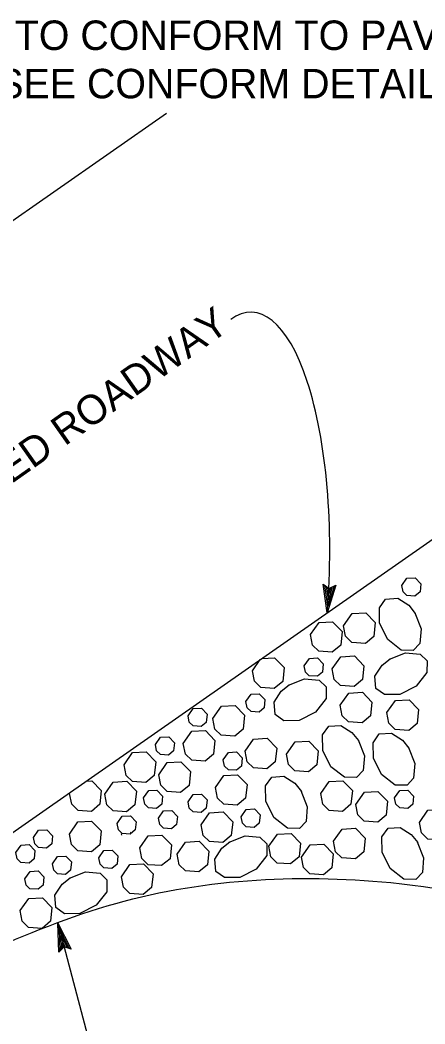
# Model space of a CAD drawing. Extents: x 6709491 to 6710959, y 1869789 to 1870763.
# Drawn here: x 6710515.2 to 6710597.8, y 1870323.8 to 1870528.2 of the extents above; entities that cross this region are included whole.
import ezdxf

# ---------------------------------------------------------------- set-up
doc = ezdxf.new("R2010")
doc.units = 0
for name, color, linetype in [('56 Stg 3 Anno', 7, 'Continuous'), ('57 Undefined', 7, 'Continuous'), ('60 Nongeo Data', 7, 'Continuous')]:
    doc.layers.add(name, color=color, linetype=linetype)

msp = doc.modelspace()

# ---------------------------------------------------------------- linework, layer by layer
at = {"layer": '56 Stg 3 Anno'}
for p, q in [((6710577.87, 1870407.51), (6710577.07, 1870413.35)), ((6710577.07, 1870413.35), (6710577.07, 1870413.35)), ((6710577.07, 1870413.35), (6710578.28, 1870412.48)), ((6710577.98, 1870408.84), (6710577.39, 1870413.1)), ((6710578.09, 1870410.15), (6710577.71, 1870412.9)), ((6710579.62, 1870413.14), (6710577.87, 1870407.51)), ((6710579.26, 1870412.96), (6710577.98, 1870408.83)), ((6710578.2, 1870411.47), (6710578.04, 1870412.65)), ((6710578.9, 1870412.77), (6710578.09, 1870410.15)), ((6710578.56, 1870412.63), (6710578.2, 1870411.47)), ((6710578.28, 1870412.48), (6710579.62, 1870413.14)), ((6710579.62, 1870413.14), (6710579.62, 1870413.14)), ((6710577.87, 1870407.51), (6710577.87, 1870407.51)), ((6710522.92, 1870344.3), (6710533.94, 1870302.96)), ((6710523.16, 1870338.4), (6710522.92, 1870344.3)), ((6710522.92, 1870344.3), (6710522.92, 1870344.3)), ((6710522.92, 1870344.3), (6710525.64, 1870339.06)), ((6710523.44, 1870338.69), (6710523.26, 1870343.02)), ((6710523.27, 1870343.01), (6710525.25, 1870339.19)), ((6710523.72, 1870339), (6710523.6, 1870341.74)), ((6710523.6, 1870341.74), (6710524.88, 1870339.27)), ((6710523.99, 1870339.25), (6710523.94, 1870340.46)), ((6710523.94, 1870340.46), (6710524.49, 1870339.4)), ((6710524.21, 1870339.48), (6710523.16, 1870338.4)), ((6710523.16, 1870338.4), (6710523.16, 1870338.4)), ((6710525.64, 1870339.06), (6710524.21, 1870339.48)), ((6710525.64, 1870339.06), (6710525.64, 1870339.06))]:
    msp.add_line(p, q, dxfattribs=at)
msp.add_ellipse((6710561.04, 1870416.49), major_axis=(1.41, 52.24), ratio=0.331, start_param=4.548521, end_param=6.530169, dxfattribs=at)
at = {"layer": '60 Nongeo Data'}
for p, q in [((6710438.76, 1870435.1), (6710545.07, 1870509.22)), ((6710451.72, 1870319.56), (6710722.11, 1870508.07))]:
    msp.add_line(p, q, dxfattribs=at)
for points in [[(6710593.08, 1870413.05), (6710594.12, 1870414.54), (6710595.79, 1870414.63), (6710596.95, 1870413.43), (6710596.78, 1870411.75), (6710595.75, 1870410.89), (6710594.11, 1870411.01), (6710593.33, 1870411.76), (6710593.08, 1870413.05)], [(6710595.71, 1870407.53), (6710597, 1870404.28), (6710596.74, 1870401.29), (6710595.39, 1870399.87), (6710592.96, 1870399.92), (6710590.21, 1870402.07), (6710588.54, 1870405.41), (6710588.49, 1870408.54), (6710589.74, 1870410.31), (6710592.25, 1870410.48), (6710594.48, 1870409.05), (6710595.79, 1870407.4)], [(6710581.2, 1870404.88), (6710582.94, 1870407.36), (6710585.71, 1870407.52), (6710587.65, 1870405.52), (6710587.37, 1870402.71), (6710585.65, 1870401.28), (6710582.91, 1870401.48), (6710581.62, 1870402.73), (6710581.2, 1870404.88)], [(6710574.45, 1870403.07), (6710576.19, 1870405.54), (6710578.97, 1870405.7), (6710580.9, 1870403.7), (6710580.62, 1870400.9), (6710578.9, 1870399.47), (6710576.16, 1870399.67), (6710574.87, 1870400.92), (6710574.45, 1870403.07)], [(6710590.55, 1870398.08), (6710593.81, 1870399.37), (6710596.79, 1870399.11), (6710598.21, 1870397.76), (6710598.17, 1870395.33), (6710596.01, 1870392.58), (6710592.68, 1870390.91), (6710589.54, 1870390.86), (6710587.77, 1870392.11), (6710587.6, 1870394.61), (6710589.04, 1870396.85), (6710590.68, 1870398.16)], [(6710564.53, 1870398.21), (6710567.14, 1870398.36), (6710569.07, 1870396.35), (6710568.79, 1870393.55), (6710567.08, 1870392.12), (6710564.34, 1870392.32), (6710563.05, 1870393.57), (6710562.63, 1870395.72)], [(6710562.63, 1870395.72), (6710564.22, 1870397.99)], [(6710564.22, 1870397.99), (6710564.22, 1870397.99)], [(6710573.18, 1870396.74), (6710574.22, 1870398.22), (6710575.89, 1870398.32), (6710577.05, 1870397.12), (6710576.88, 1870395.44), (6710575.85, 1870394.58), (6710574.2, 1870394.7), (6710573.43, 1870395.45), (6710573.18, 1870396.74)], [(6710578.88, 1870396.1), (6710580.62, 1870398.57), (6710583.4, 1870398.73), (6710585.33, 1870396.73), (6710585.05, 1870393.93), (6710583.33, 1870392.5), (6710580.59, 1870392.7), (6710579.3, 1870393.95), (6710578.88, 1870396.1)], [(6710570, 1870392.78), (6710573.25, 1870394.07), (6710576.24, 1870393.81), (6710577.66, 1870392.46), (6710577.62, 1870390.03), (6710575.46, 1870387.28), (6710572.13, 1870385.61), (6710568.99, 1870385.55), (6710567.22, 1870386.81), (6710567.05, 1870389.31), (6710568.49, 1870391.55), (6710570.13, 1870392.86)], [(6710580.52, 1870388.69), (6710582.25, 1870391.17), (6710585.03, 1870391.32), (6710586.96, 1870389.32), (6710586.68, 1870386.52), (6710584.97, 1870385.09), (6710582.23, 1870385.29), (6710580.94, 1870386.54), (6710580.52, 1870388.69)], [(6710561.3, 1870389.46), (6710562.34, 1870390.94), (6710564.01, 1870391.04), (6710565.17, 1870389.84), (6710565, 1870388.15), (6710563.97, 1870387.3), (6710562.33, 1870387.42), (6710561.55, 1870388.17), (6710561.3, 1870389.46)], [(6710590.03, 1870387.18), (6710591.76, 1870389.65), (6710594.54, 1870389.81), (6710596.47, 1870387.81), (6710596.19, 1870385), (6710594.48, 1870383.58), (6710591.74, 1870383.77), (6710590.45, 1870385.03), (6710590.03, 1870387.18)], [(6710549.5, 1870386.51), (6710550.54, 1870388), (6710552.21, 1870388.09), (6710553.36, 1870386.89), (6710553.2, 1870385.21), (6710552.17, 1870384.35), (6710550.52, 1870384.47), (6710549.75, 1870385.22), (6710549.5, 1870386.51)], [(6710554.55, 1870386), (6710556.29, 1870388.48), (6710559.07, 1870388.64), (6710561, 1870386.64), (6710560.72, 1870383.83), (6710559, 1870382.4), (6710556.26, 1870382.6), (6710554.97, 1870383.85), (6710554.55, 1870386)], [(6710548.52, 1870380.9), (6710550.26, 1870383.38), (6710553.03, 1870383.54), (6710554.96, 1870381.53), (6710554.68, 1870378.73), (6710552.97, 1870377.3), (6710550.23, 1870377.5), (6710548.94, 1870378.75), (6710548.52, 1870380.9)], [(6710584.14, 1870381.64), (6710585.43, 1870378.39), (6710585.17, 1870375.4), (6710583.82, 1870373.98), (6710581.39, 1870374.02), (6710578.63, 1870376.18), (6710576.97, 1870379.51), (6710576.91, 1870382.65), (6710578.17, 1870384.42), (6710580.67, 1870384.59), (6710582.91, 1870383.15), (6710584.22, 1870381.51)], [(6710594.45, 1870380.06), (6710595.74, 1870376.81), (6710595.48, 1870373.82), (6710594.13, 1870372.4), (6710591.7, 1870372.45), (6710588.95, 1870374.6), (6710587.28, 1870377.94), (6710587.23, 1870381.07), (6710588.48, 1870382.84), (6710590.98, 1870383.01), (6710593.22, 1870381.58), (6710594.53, 1870379.93)], [(6710542.84, 1870380.68), (6710543.88, 1870382.17), (6710545.55, 1870382.26), (6710546.7, 1870381.06), (6710546.54, 1870379.38), (6710545.51, 1870378.52), (6710543.86, 1870378.64), (6710543.09, 1870379.39), (6710542.84, 1870380.68)], [(6710561.11, 1870379.34), (6710562.85, 1870381.81), (6710565.63, 1870381.97), (6710567.56, 1870379.97), (6710567.28, 1870377.17), (6710565.56, 1870375.74), (6710562.82, 1870375.94), (6710561.53, 1870377.19), (6710561.11, 1870379.34)], [(6710569.58, 1870378.76), (6710571.32, 1870381.24), (6710574.1, 1870381.39), (6710576.03, 1870379.39), (6710575.75, 1870376.59), (6710574.04, 1870375.16), (6710571.29, 1870375.36), (6710570, 1870376.61), (6710569.58, 1870378.76)], [(6710536.45, 1870376.56), (6710538.19, 1870379.04), (6710540.96, 1870379.19), (6710542.89, 1870377.19), (6710542.61, 1870374.39), (6710540.9, 1870372.96), (6710538.16, 1870373.16), (6710536.87, 1870374.41), (6710536.45, 1870376.56)], [(6710556.68, 1870377.61), (6710557.73, 1870379.1), (6710559.39, 1870379.19), (6710560.55, 1870377.99), (6710560.38, 1870376.31), (6710559.36, 1870375.45), (6710557.71, 1870375.57), (6710556.93, 1870376.32), (6710556.68, 1870377.61)], [(6710543.52, 1870374.55), (6710545.26, 1870377.03), (6710548.04, 1870377.19), (6710549.97, 1870375.18), (6710549.69, 1870372.38), (6710547.98, 1870370.95), (6710545.23, 1870371.15), (6710543.94, 1870372.4), (6710543.52, 1870374.55)], [(6710528.75, 1870373.26), (6710529.87, 1870373.33), (6710531.8, 1870371.33), (6710531.52, 1870368.52), (6710529.8, 1870367.09), (6710527.06, 1870367.29), (6710525.77, 1870368.54), (6710525.35, 1870370.69)], [(6710532.5, 1870370.59), (6710534.24, 1870373.06), (6710537.02, 1870373.22), (6710538.95, 1870371.22), (6710538.67, 1870368.42), (6710536.96, 1870366.99), (6710534.21, 1870367.19), (6710532.93, 1870368.44), (6710532.51, 1870370.59)], [(6710555.06, 1870371.92), (6710556.8, 1870374.39), (6710559.58, 1870374.55), (6710561.51, 1870372.55), (6710561.23, 1870369.75), (6710559.51, 1870368.32), (6710556.77, 1870368.52), (6710555.48, 1870369.77), (6710555.06, 1870371.92)], [(6710572.51, 1870371.3), (6710573.8, 1870368.04), (6710573.54, 1870365.05), (6710572.19, 1870363.63), (6710569.76, 1870363.68), (6710567.01, 1870365.83), (6710565.34, 1870369.17), (6710565.29, 1870372.31), (6710566.54, 1870374.07), (6710569.05, 1870374.24), (6710571.28, 1870372.81), (6710572.59, 1870371.16)], [(6710576.54, 1870370.7), (6710578.28, 1870373.17), (6710581.06, 1870373.33), (6710582.99, 1870371.33), (6710582.71, 1870368.52), (6710580.99, 1870367.09), (6710578.25, 1870367.29), (6710576.96, 1870368.54), (6710576.54, 1870370.69)], [(6710540.42, 1870369.83), (6710541.46, 1870371.31), (6710543.13, 1870371.4), (6710544.29, 1870370.2), (6710544.12, 1870368.52), (6710543.09, 1870367.67), (6710541.45, 1870367.78), (6710540.67, 1870368.53), (6710540.42, 1870369.82)], [(6710583.7, 1870368.5), (6710585.44, 1870370.98), (6710588.21, 1870371.14), (6710590.15, 1870369.14), (6710589.87, 1870366.33), (6710588.15, 1870364.9), (6710585.41, 1870365.1), (6710584.12, 1870366.35), (6710583.7, 1870368.5)], [(6710591.61, 1870369.83), (6710592.66, 1870371.31), (6710594.32, 1870371.4), (6710595.48, 1870370.2), (6710595.31, 1870368.52), (6710594.28, 1870367.67), (6710592.64, 1870367.78), (6710591.86, 1870368.53), (6710591.61, 1870369.82)], [(6710549.5, 1870369.03), (6710550.54, 1870370.51), (6710552.21, 1870370.6), (6710553.36, 1870369.4), (6710553.2, 1870367.72), (6710552.17, 1870366.86), (6710550.52, 1870366.98), (6710549.75, 1870367.73), (6710549.5, 1870369.02)], [(6710543.46, 1870365.68), (6710544.51, 1870367.17), (6710546.17, 1870367.26), (6710547.33, 1870366.06), (6710547.16, 1870364.38), (6710546.13, 1870363.52), (6710544.49, 1870363.64), (6710543.72, 1870364.39), (6710543.46, 1870365.68)], [(6710552.15, 1870364.34), (6710553.88, 1870366.82), (6710556.66, 1870366.97), (6710558.59, 1870364.97), (6710558.31, 1870362.17), (6710556.6, 1870360.74), (6710553.86, 1870360.94), (6710552.57, 1870362.19), (6710552.15, 1870364.34)], [(6710560.31, 1870365.99), (6710561.35, 1870367.47), (6710563.02, 1870367.57), (6710564.18, 1870366.36), (6710564.01, 1870364.68), (6710562.98, 1870363.83), (6710561.34, 1870363.95), (6710560.56, 1870364.7), (6710560.31, 1870365.99)], [(6710596.67, 1870364.85), (6710598.41, 1870367.32), (6710601.18, 1870367.48), (6710603.11, 1870365.48), (6710602.83, 1870362.68), (6710601.12, 1870361.25), (6710598.38, 1870361.45), (6710597.09, 1870362.7), (6710596.67, 1870364.85)], [(6710525.31, 1870362.46), (6710527.05, 1870364.94), (6710529.83, 1870365.1), (6710531.76, 1870363.09), (6710531.48, 1870360.29), (6710529.77, 1870358.86), (6710527.02, 1870359.06), (6710525.73, 1870360.31), (6710525.31, 1870362.46)], [(6710535.04, 1870364.6), (6710536.08, 1870366.09), (6710537.75, 1870366.19), (6710538.9, 1870364.98), (6710538.74, 1870363.3), (6710537.71, 1870362.44), (6710536.06, 1870362.56), (6710535.29, 1870363.31), (6710535.04, 1870364.6)], [(6710517.99, 1870361.75), (6710519.03, 1870363.24), (6710520.7, 1870363.33), (6710521.86, 1870362.13), (6710521.69, 1870360.45), (6710520.66, 1870359.59), (6710519.01, 1870359.71), (6710518.24, 1870360.46), (6710517.99, 1870361.75)], [(6710536, 1870362.26), (6710535.94, 1870362.53)], [(6710537.77, 1870362.76), (6710537.91, 1870362.87)], [(6710565.96, 1870359.97), (6710567.7, 1870362.45), (6710570.48, 1870362.61), (6710572.41, 1870360.61), (6710572.13, 1870357.8), (6710570.41, 1870356.37), (6710567.67, 1870356.57), (6710566.38, 1870357.82), (6710565.96, 1870359.97)], [(6710579.15, 1870361.01), (6710580.89, 1870363.48), (6710583.66, 1870363.64), (6710585.59, 1870361.64), (6710585.32, 1870358.83), (6710583.6, 1870357.41), (6710580.86, 1870357.6), (6710579.57, 1870358.86), (6710579.15, 1870361.01)], [(6710596.22, 1870360.88), (6710597.51, 1870357.63), (6710597.26, 1870354.64), (6710595.9, 1870353.22), (6710593.48, 1870353.26), (6710590.72, 1870355.42), (6710589.06, 1870358.75), (6710589, 1870361.89), (6710590.26, 1870363.66), (6710592.76, 1870363.82), (6710595, 1870362.39), (6710596.31, 1870360.75)], [(6710539.64, 1870359.63), (6710541.38, 1870362.1), (6710544.15, 1870362.26), (6710546.09, 1870360.26), (6710545.81, 1870357.45), (6710544.09, 1870356.03), (6710541.35, 1870356.23), (6710540.06, 1870357.48), (6710539.64, 1870359.63)], [(6710547.26, 1870358.36), (6710549, 1870360.84), (6710551.78, 1870361), (6710553.7, 1870359), (6710553.43, 1870356.19), (6710551.71, 1870354.76), (6710548.97, 1870354.96), (6710547.68, 1870356.21), (6710547.26, 1870358.36)], [(6710557.9, 1870360.82), (6710561.16, 1870362.11), (6710564.14, 1870361.85), (6710565.57, 1870360.5), (6710565.52, 1870358.08), (6710563.36, 1870355.32), (6710560.03, 1870353.65), (6710556.89, 1870353.6), (6710555.12, 1870354.86), (6710554.96, 1870357.36), (6710556.39, 1870359.59), (6710558.03, 1870360.9)], [(6710572.64, 1870357.78), (6710574.38, 1870360.26), (6710577.16, 1870360.41), (6710579.09, 1870358.41), (6710578.81, 1870355.61), (6710577.1, 1870354.18), (6710574.35, 1870354.38), (6710573.06, 1870355.63), (6710572.65, 1870357.78)], [(6710514.4, 1870358.73), (6710515.44, 1870360.22), (6710517.11, 1870360.31), (6710518.27, 1870359.11), (6710518.1, 1870357.43), (6710517.07, 1870356.57), (6710515.43, 1870356.69), (6710514.65, 1870357.44), (6710514.4, 1870358.73)], [(6710531.31, 1870357.63), (6710532.35, 1870359.12), (6710534.02, 1870359.21), (6710535.18, 1870358.01), (6710535.01, 1870356.33), (6710533.98, 1870355.47), (6710532.33, 1870355.59), (6710531.56, 1870356.34), (6710531.31, 1870357.63)], [(6710521.85, 1870356.4), (6710522.9, 1870357.89), (6710524.56, 1870357.99), (6710525.72, 1870356.78), (6710525.55, 1870355.1), (6710524.52, 1870354.24), (6710522.88, 1870354.36), (6710522.11, 1870355.11), (6710521.85, 1870356.4)], [(6710535.9, 1870353.77), (6710537.64, 1870356.25), (6710540.42, 1870356.41), (6710542.35, 1870354.4), (6710542.07, 1870351.6), (6710540.35, 1870350.17), (6710537.61, 1870350.37), (6710536.32, 1870351.62), (6710535.9, 1870353.77)], [(6710516.23, 1870353.38), (6710517.28, 1870354.87), (6710518.94, 1870354.96), (6710520.1, 1870353.76), (6710519.94, 1870352.08), (6710518.91, 1870351.22), (6710517.26, 1870351.34), (6710516.49, 1870352.09), (6710516.24, 1870353.38)], [(6710525.3, 1870353.48), (6710528.55, 1870354.77), (6710531.54, 1870354.51), (6710532.96, 1870353.16), (6710532.92, 1870350.73), (6710530.76, 1870347.97), (6710527.43, 1870346.31), (6710524.29, 1870346.25), (6710522.52, 1870347.51), (6710522.36, 1870350.01), (6710523.79, 1870352.25), (6710525.43, 1870353.56)], [(6710515.27, 1870346.87), (6710517.01, 1870349.35), (6710519.79, 1870349.51), (6710521.72, 1870347.5), (6710521.44, 1870344.7), (6710519.73, 1870343.27), (6710516.98, 1870343.47), (6710515.69, 1870344.72), (6710515.28, 1870346.87)]]:
    msp.add_lwpolyline(points, dxfattribs=at)
msp.add_spline([(6710505.99, 1870337.51), (6710532.99, 1870347.83), (6710590.83, 1870352.57), (6710625.79, 1870346.13), (6710776.97, 1870278.77)], degree=3, dxfattribs=at)

# ---------------------------------------------------------------- texts
at = {"layer": '57 Undefined'}
for s, p in [('EXCAVATE TO CONFORM TO PAVEMENT ', (6710469.13, 1870522.1)), ('OR CURB, SEE CONFORM DETAIL', (6710469.13, 1870512.26))]:
    msp.add_text(s, height=6, dxfattribs=at).set_placement(p)
msp.add_text('EXISTING PAVED ROADWAY', height=6, rotation=35.1601, dxfattribs=at).set_placement((6710467.83, 1870401.55))

doc.saveas('drawing.dxf')
